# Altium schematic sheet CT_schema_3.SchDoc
size 328 x 327 mm
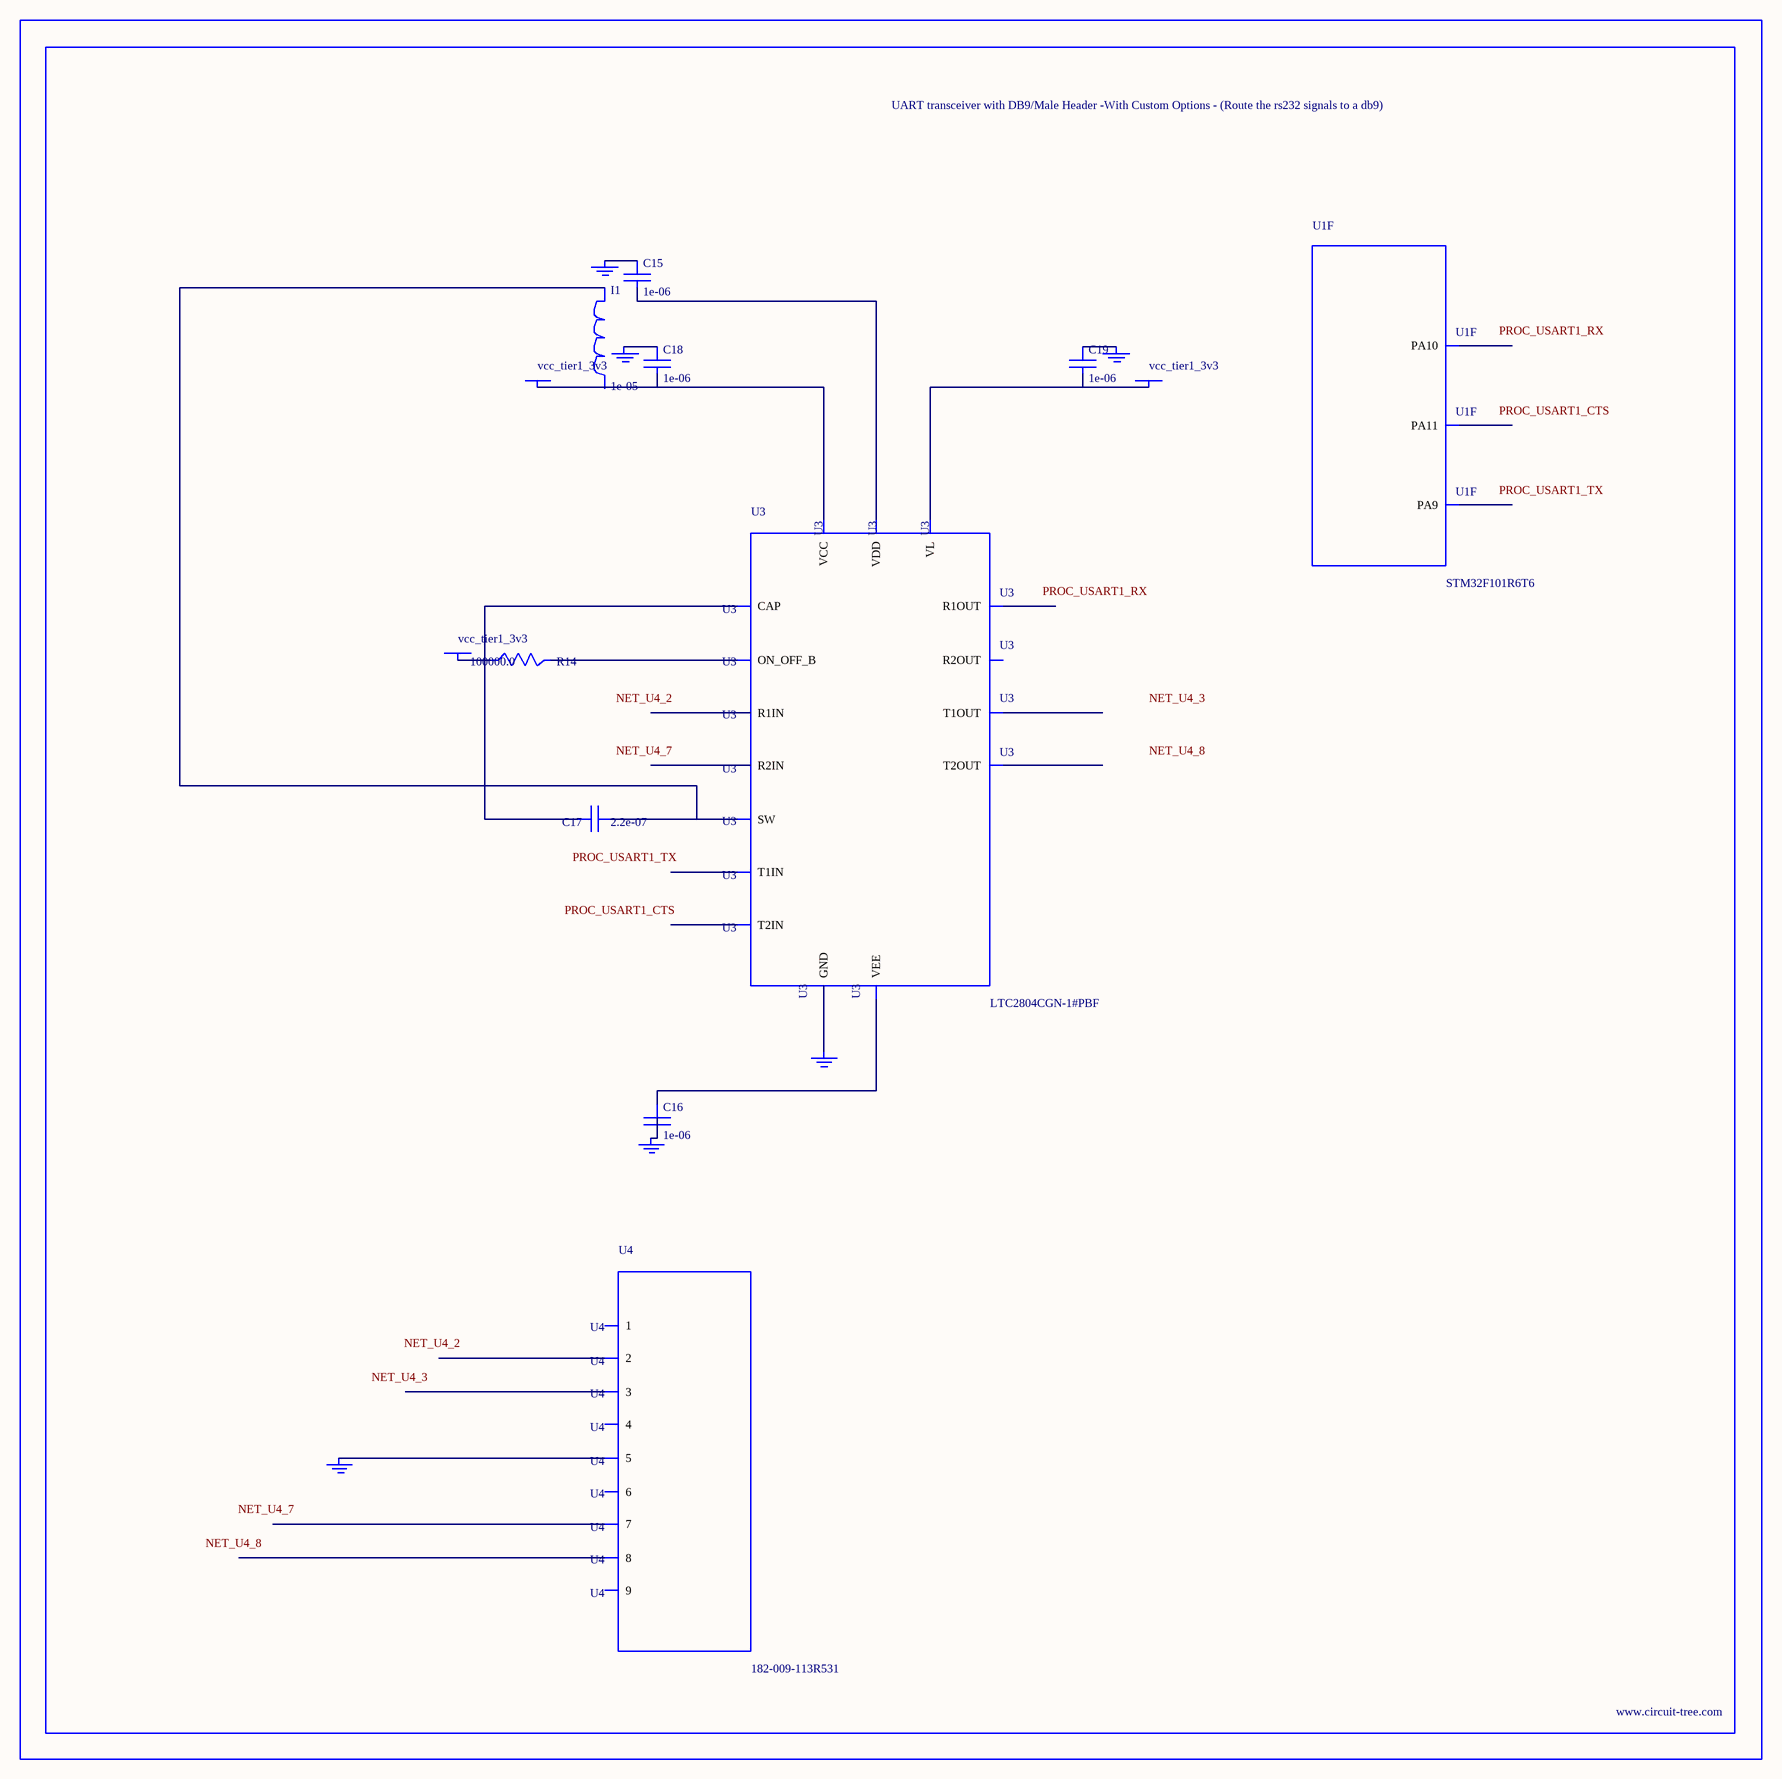
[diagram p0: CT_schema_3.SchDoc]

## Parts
BORDER2  (no value)
C15  1e-06  [C0603]
C16  1e-06  [C0603]
C17  2.2e-07  [C0603]
C18  1e-06  [C0603]
C19  1e-06  [C0603]
GND_INSTANCE_2_0  (no value)
GND_INSTANCE_2_1  (no value)
GND_INSTANCE_2_2  (no value)
GND_INSTANCE_2_3  (no value)
GND_INSTANCE_2_4  (no value)
GND_INSTANCE_2_5  (no value)
I1  1e-05  [L1210]
POWER_INSTANCE_2_0  vcc_tier1_3v3
POWER_INSTANCE_2_1  vcc_tier1_3v3
POWER_INSTANCE_2_2  vcc_tier1_3v3
R14  100000.0  [R0603]
U1  STM32F101R6T6  [LQFP64]  (part F of 7)
U3  LTC2804CGN-1#PBF  [SSOP-16]
U4  182-009-113R531  [182-009-MALE]

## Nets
NetC15_1: C15.1 GND_INSTANCE_2_1.0(GND)
NetC15_2: C15.2 U3.6(VDD)
NetC16_1: C16.1 U3.9(VEE)
NetC16_2: C16.2 GND_INSTANCE_2_2.0(GND)
NetC17_1: C17.1 I1.1 U3.7(SW)
NetC17_2: C17.2 U3.10(CAP)
NetC18_1: C18.1 GND_INSTANCE_2_0.0(GND)
NetC18_2: C18.2 POWER_INSTANCE_2_0.0(PWR) U3.5(VCC)
NetC19_1: C19.1 GND_INSTANCE_2_3.0(GND)
NetC19_2: C19.2 POWER_INSTANCE_2_2.0(PWR) U3.12(VL)
NetGND_INSTANCE_2_4_0: GND_INSTANCE_2_4.0(GND) U3.8(GND)
NetGND_INSTANCE_2_5_0: GND_INSTANCE_2_5.0(GND) U4.5
NetPOWER_INSTANCE_2_1_0: POWER_INSTANCE_2_1.0(PWR) R14.1
NetR14_2: R14.2 U3.11(ON_OFF_B)

Not connected (* = marked no-connect by the designer): I1 2; U1 42(PA9) 43(PA10) 44(PA11); U3 1(R1IN) 2(R2IN) 3(T1OUT) 4(T2OUT) 13(T2IN) 14(T1IN) 15(R2OUT) 16(R1OUT); U4 1 2 3 4 6 7 8 9

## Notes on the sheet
- Labels drawn without touching a wire or pin: NET_U4_2, NET_U4_3, NET_U4_7, NET_U4_8, PROC_USART1_CTS, PROC_USART1_RX, PROC_USART1_TX

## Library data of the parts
BORDER2 = BORDER_PAGE2
C15 C16 C18 C19 = C0603C105K3RACTU
C17 = C0603C224K3RAC
GND_INSTANCE_2_0-GND_INSTANCE_2_5 = GND
I1 = CBC3225T100MR
POWER_INSTANCE_2_0-POWER_INSTANCE_2_2 = PWR
R14 = RC0603JR-07100KL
